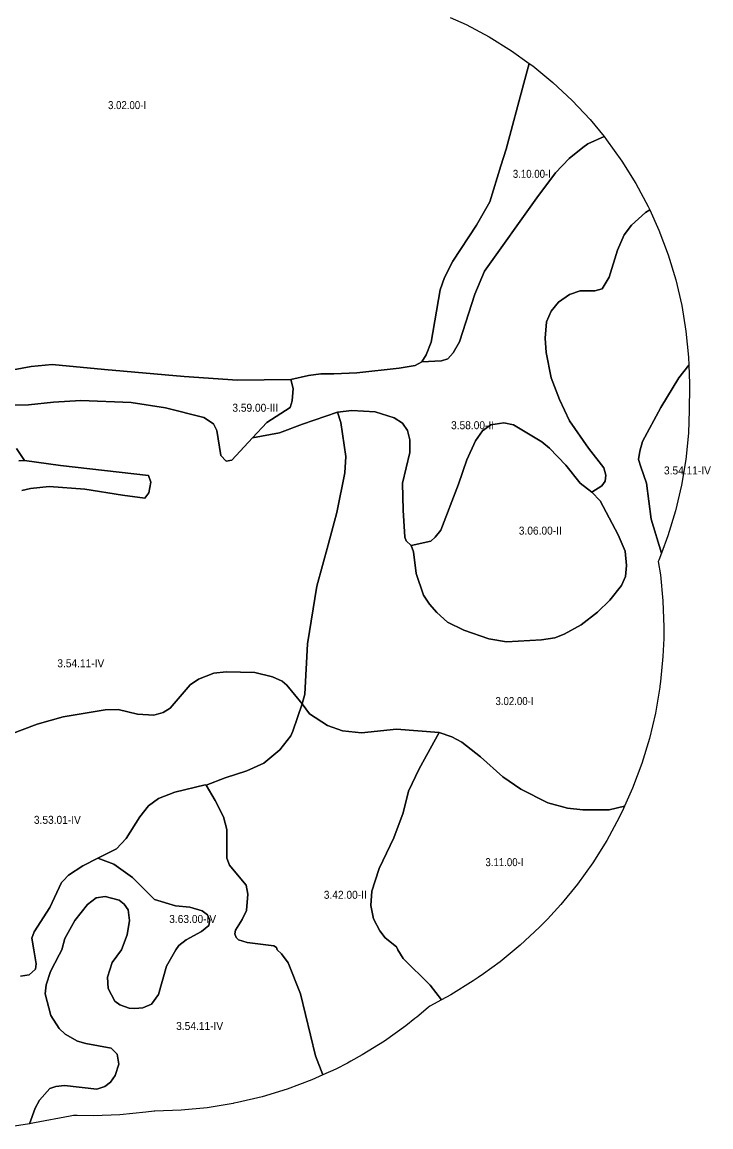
# Model space of a CAD drawing. Extents: x -591496 to -585489, y -1120610 to -1115685.
# Drawn here: x -587209 to -585489, y -1120442 to -1117681 of the extents above; entities that cross this region are included whole.
import ezdxf

# ---------------------------------------------------------------- set-up
doc = ezdxf.new("R2010")
doc.units = 0
doc.header["$LTSCALE"] = 8
doc.layers.add('40', color=7, linetype='Continuous', lineweight=25)
doc.layers.add('41', color=7, linetype='Continuous')

msp = doc.modelspace()

# ---------------------------------------------------------------- linework, layer by layer
at = {"layer": '40'}
for points in [[(-586139.893, -1117669.247), (-586100.231, -1117687.217), (-586042.52, -1117718.065), (-585986.95, -1117752.62), (-585942.401, -1117784.544), (-585956, -1117833.5), (-586000, -1117998.5), (-586013.5, -1118040), (-586041, -1118130), (-586074, -1118188.5), (-586133.5, -1118278.5), (-586154, -1118319), (-586165, -1118350.5), (-586187, -1118481), (-586199.5, -1118512.5), (-586211, -1118530), (-586227.5, -1118539), (-586267.5, -1118546), (-586373, -1118558), (-586430.5, -1118560.5), (-586463, -1118560.5), (-586494, -1118564.5), (-586538, -1118574), (-586670.5, -1118576), (-586804, -1118566.5), (-587003, -1118549.5), (-587133.5, -1118537), (-587186, -1118541.5), (-587277, -1118558.5)], [(-585778.5, -1118352.5), (-585760.5, -1118348), (-585742.5, -1118318.5), (-585722, -1118251), (-585705.5, -1118212.5), (-585687, -1118188.5), (-585652.5, -1118157), (-585641.639, -1118150.648), (-585618.64, -1118201.407), (-585595.59, -1118262.651), (-585576.594, -1118325.271), (-585561.735, -1118389), (-585551.075, -1118453.564), (-585544.661, -1118518.687), (-585544.009, -1118538.605)], [(-585544.009, -1118538.605), (-585568.5, -1118570.5), (-585613.5, -1118644), (-585659.5, -1118729.5), (-585666.5, -1118753.5), (-585669.5, -1118774.5), (-585663.5, -1118792.5), (-585650, -1118833), (-585638, -1118923), (-585612.459, -1119008.38), (-585619.111, -1119026.053), (-585620.493, -1119029.104), (-585614.945, -1119062.704), (-585608.531, -1119127.827), (-585606.39, -1119193.23), (-585606.611, -1119214.278), (-585606.772, -1119221.878), (-585608.691, -1119266.233), (-585614.81, -1119329.094), (-585616.34, -1119340.924), (-585616.635, -1119343.186), (-585627.295, -1119407.75), (-585642.154, -1119471.479), (-585661.15, -1119534.1), (-585684.2, -1119595.343), (-585704.651, -1119640.678), (-585742.5, -1119649.5), (-585809, -1119650), (-585847, -1119645.5), (-585896, -1119632), (-585963.5, -1119598.5), (-586008.5, -1119567), (-586064.5, -1119517.5), (-586111, -1119481), (-586136, -1119467), (-586167, -1119456.5), (-586274, -1119448.5), (-586361, -1119457), (-586408.5, -1119452), (-586446, -1119439), (-586491.5, -1119410), (-586509.5, -1119385), (-586503, -1119361), (-586496.5, -1119235), (-586472.5, -1119091), (-586444.5, -1118987.5), (-586423, -1118906.5), (-586402.5, -1118807.5), (-586400, -1118767), (-586412.5, -1118681.5), (-586421, -1118656), (-586385.5, -1118652), (-586327, -1118655), (-586280, -1118670.5), (-586259, -1118683.5), (-586246.5, -1118701.5), (-586240.5, -1118725.5), (-586241, -1118757), (-586258.5, -1118833.5), (-586257.5, -1118901), (-586253, -1118968.5), (-586249.5, -1118977.5), (-586237.5, -1118989.5), (-586231.5, -1119005), (-586225, -1119059), (-586206.5, -1119113), (-586191.5, -1119135.5), (-586173, -1119157), (-586146.5, -1119180.5), (-586105.5, -1119201), (-586043, -1119222), (-585999.5, -1119230), (-585911.5, -1119225), (-585878.5, -1119219.5), (-585855, -1119211), (-585812.5, -1119187), (-585772, -1119155.5), (-585741.5, -1119126), (-585712, -1119089), (-585702, -1119066.5), (-585699.5, -1119039.5), (-585703, -1119003.5), (-585720, -1118962.5), (-585765.5, -1118877.5), (-585786.5, -1118856), (-585761.5, -1118840), (-585753, -1118828), (-585751, -1118813), (-585756.5, -1118795), (-585794.5, -1118745.5), (-585841.5, -1118678), (-585867, -1118624), (-585887.5, -1118570), (-585900, -1118507), (-585903, -1118471), (-585899, -1118430.5), (-585888, -1118403.5), (-585869.5, -1118381), (-585842, -1118362), (-585815.5, -1118353), (-585778.5, -1118352.5)], [(-587277, -1118558.5), (-587186, -1118541.5), (-587133.5, -1118537), (-587003, -1118549.5), (-586804, -1118566.5), (-586670.5, -1118576), (-586538, -1118574), (-586531.5, -1118596.5), (-586534, -1118628), (-586539.5, -1118644), (-586598, -1118682), (-586633.572, -1118720.434), (-586685, -1118776), (-586699, -1118778), (-586712.5, -1118764.5), (-586722.5, -1118701.5), (-586731, -1118685), (-586755, -1118669), (-586850.5, -1118645), (-586936.5, -1118632), (-587062, -1118627), (-587130.5, -1118631), (-587193, -1118638), (-587237, -1118638.5)], [(-587237, -1118638.5), (-587193, -1118638), (-587130.5, -1118631), (-587062, -1118627), (-586936.5, -1118632), (-586850.5, -1118645), (-586755, -1118669), (-586731, -1118685)], [(-586633.572, -1118720.434), (-586566, -1118707.5), (-586508.5, -1118686), (-586421, -1118656), (-586412.5, -1118681.5), (-586400, -1118767), (-586402.5, -1118807.5), (-586423, -1118906.5), (-586444.5, -1118987.5), (-586472.5, -1119091), (-586496.5, -1119235), (-586503, -1119361), (-586509.5, -1119385), (-586547.5, -1119338), (-586559, -1119328), (-586583.5, -1119317), (-586627.5, -1119306.5), (-586699, -1119304.5), (-586730, -1119308.5), (-586768.5, -1119323), (-586789, -1119337.5), (-586839, -1119396), (-586856.5, -1119406.5), (-586879.5, -1119413), (-586920.5, -1119411), (-586969, -1119399), (-587001, -1119400), (-587106, -1119417.5), (-587171, -1119436), (-587271, -1119473)], [(-586731, -1118685), (-586722.5, -1118701.5), (-586712.5, -1118764.5), (-586699, -1118778), (-586685, -1118776), (-586633.572, -1118720.434)], [(-587209.5, -1118851.5), (-587188, -1118846.5), (-587141, -1118842), (-587052, -1118848), (-586958, -1118863), (-586902.5, -1118870.5), (-586892.5, -1118857.5), (-586887, -1118830.5), (-586893, -1118814), (-587112.5, -1118789.5), (-587202.5, -1118777), (-587222.5, -1118746.5)], [(-587222.5, -1118746.5), (-587202.5, -1118777), (-587217, -1118777.5)], [(-587217, -1118777.5), (-587202.5, -1118777), (-587112.5, -1118789.5), (-586893, -1118814), (-586887, -1118830.5), (-586892.5, -1118857.5), (-586902.5, -1118870.5), (-586958, -1118863), (-587052, -1118848), (-587141, -1118842), (-587188, -1118846.5), (-587209.5, -1118851.5)], [(-587271, -1119473), (-587171, -1119436), (-587106, -1119417.5), (-587001, -1119400), (-586969, -1119399), (-586920.5, -1119411), (-586879.5, -1119413), (-586856.5, -1119406.5), (-586839, -1119396), (-586789, -1119337.5), (-586768.5, -1119323), (-586730, -1119308.5), (-586699, -1119304.5), (-586627.5, -1119306.5), (-586583.5, -1119317), (-586559, -1119328), (-586547.5, -1119338), (-586509.5, -1119385), (-586532.5, -1119453.5), (-586538, -1119464.5), (-586565.5, -1119500), (-586605.5, -1119533), (-586648, -1119552), (-586702, -1119570), (-586749, -1119588), (-586751.5, -1119587.5), (-586827.5, -1119606), (-586868.5, -1119621), (-586893, -1119640), (-586915, -1119667), (-586948.5, -1119721), (-586973, -1119747.5), (-587019.5, -1119770.5), (-587057.5, -1119789.5), (-587093, -1119813), (-587106.513, -1119826.9), (-587110.5, -1119831), (-587139.5, -1119894), (-587178.5, -1119955), (-587184.5, -1119970.5), (-587179.632, -1120000), (-587174, -1120034.5), (-587175.5, -1120048), (-587191.5, -1120062), (-587213, -1120065)], [(-586749, -1119588), (-586726.5, -1119626.5), (-586705.5, -1119667), (-586697.5, -1119698.5), (-586697.5, -1119770.5), (-586691, -1119788), (-586658.713, -1119826.9), (-586649.5, -1119838), (-586645, -1119860.5), (-586648.5, -1119901), (-586659, -1119923.5), (-586675.5, -1119950.5), (-586677.5, -1119959.5), (-586674, -1119968.5), (-586668, -1119974.5), (-586646.5, -1119981.5), (-586580, -1119990), (-586573.5, -1119993.5), (-586571.572, -1120000), (-586561, -1120009.5), (-586544, -1120032), (-586513.5, -1120109.5), (-586476, -1120264.5), (-586457.504, -1120312.061), (-586485.287, -1120324.65), (-586546.531, -1120347.7), (-586609.151, -1120366.696), (-586671.035, -1120381.187), (-586680.245, -1120383.037), (-586682.09, -1120383.405), (-586746.654, -1120394.065), (-586811.777, -1120400.479), (-586877.18, -1120402.62), (-586878.011, -1120402.62), (-586878.678, -1120402.619), (-586899.574, -1120405.595), (-586964.697, -1120412.009), (-587030.1, -1120414.15), (-587071.294, -1120413.301), (-587078.89, -1120413.33), (-587080.378, -1120413.329), (-587084.34, -1120414.125), (-587088.816, -1120415.005), (-587178.066, -1120432.335), (-587190.445, -1120434.35), (-587176, -1120395), (-587165, -1120375.5), (-587139.5, -1120346.5), (-587124.5, -1120341), (-587103, -1120338.5), (-587022, -1120347.5), (-587002, -1120341), (-586988, -1120330.5), (-586976, -1120313.5), (-586967.5, -1120285.5), (-586971, -1120260.5), (-586986.5, -1120245.5), (-587049.5, -1120234), (-587070.5, -1120227.5), (-587101.5, -1120210.5), (-587116.5, -1120196.5), (-587137, -1120163.5), (-587151, -1120109.5), (-587148.5, -1120087), (-587138, -1120053.5), (-587116.5, -1120012.5), (-587109.595, -1120000), (-587102, -1119971.5), (-587077, -1119926.5), (-587045.5, -1119886), (-587024, -1119869.5), (-587001, -1119866), (-586966, -1119875.5), (-586953.5, -1119885.5), (-586943.5, -1119899.5), (-586940.5, -1119926.5), (-586946.5, -1119962.5), (-586960.812, -1120000), (-586984, -1120031.5), (-586995.5, -1120067.5), (-586994, -1120096.5), (-586977, -1120127.5), (-586965, -1120137), (-586941.5, -1120145.5), (-586927.5, -1120146.5), (-586907.5, -1120144.5), (-586886, -1120135), (-586868.5, -1120111), (-586848.5, -1120040.5), (-586824.732, -1120000), (-586817, -1119988.5), (-586799.5, -1119975), (-586760.5, -1119953.5), (-586742.5, -1119939), (-586740, -1119925.5), (-586746, -1119912), (-586759, -1119902), (-586790, -1119893), (-586826, -1119890), (-586878.5, -1119873.5), (-586925.1, -1119826.9)], [(-586925.1, -1119826.9), (-586933.5, -1119818.5), (-586980, -1119785.5), (-587019.5, -1119770.5), (-586973, -1119747.5), (-586948.5, -1119721), (-586915, -1119667), (-586893, -1119640), (-586868.5, -1119621), (-586827.5, -1119606), (-586751.5, -1119587.5), (-586749, -1119588)], [(-587213, -1120065), (-587191.5, -1120062), (-587175.5, -1120048), (-587174, -1120034.5), (-587179.632, -1120000), (-587184.5, -1119970.5), (-587178.5, -1119955), (-587139.5, -1119894), (-587110.5, -1119831), (-587106.513, -1119826.9), (-587093, -1119813), (-587057.5, -1119789.5), (-587019.5, -1119770.5), (-586980, -1119785.5), (-586933.5, -1119818.5), (-586925.1, -1119826.9), (-586878.5, -1119873.5), (-586826, -1119890), (-586790, -1119893), (-586759, -1119902), (-586746, -1119912), (-586740, -1119925.5), (-586742.5, -1119939), (-586760.5, -1119953.5), (-586799.5, -1119975), (-586817, -1119988.5), (-586824.732, -1120000), (-586848.5, -1120040.5), (-586868.5, -1120111), (-586886, -1120135), (-586907.5, -1120144.5), (-586927.5, -1120146.5), (-586941.5, -1120145.5), (-586965, -1120137), (-586977, -1120127.5), (-586994, -1120096.5), (-586995.5, -1120067.5), (-586984, -1120031.5), (-586960.812, -1120000), (-586946.5, -1119962.5), (-586940.5, -1119926.5), (-586943.5, -1119899.5), (-586953.5, -1119885.5), (-586966, -1119875.5), (-587001, -1119866), (-587024, -1119869.5), (-587045.5, -1119886), (-587077, -1119926.5), (-587102, -1119971.5), (-587109.595, -1120000), (-587116.5, -1120012.5), (-587138, -1120053.5), (-587148.5, -1120087), (-587151, -1120109.5), (-587137, -1120163.5), (-587116.5, -1120196.5), (-587101.5, -1120210.5), (-587070.5, -1120227.5), (-587049.5, -1120234), (-586986.5, -1120245.5), (-586971, -1120260.5), (-586967.5, -1120285.5), (-586976, -1120313.5), (-586988, -1120330.5), (-587002, -1120341), (-587022, -1120347.5), (-587103, -1120338.5), (-587124.5, -1120341), (-587139.5, -1120346.5), (-587165, -1120375.5), (-587176, -1120395), (-587190.445, -1120434.35), (-587238.154, -1120442.115)]]:
    msp.add_lwpolyline(points, dxfattribs=at)
for points in [[(-585755.742, -1117967.317), (-585796, -1117985), (-585809, -1117994.5), (-585843, -1118022), (-585876.5, -1118058), (-585923.5, -1118120.5), (-586054, -1118303.5), (-586078.5, -1118361), (-586116.5, -1118480.5), (-586132, -1118507.5), (-586146, -1118522.5), (-586161.5, -1118527.5), (-586211, -1118530), (-586199.5, -1118512.5), (-586187, -1118481), (-586165, -1118350.5), (-586154, -1118319), (-586133.5, -1118278.5), (-586074, -1118188.5), (-586041, -1118130), (-586013.5, -1118040), (-586000, -1117998.5), (-585956, -1117833.5), (-585942.401, -1117784.544), (-585933.759, -1117790.737), (-585883.174, -1117832.25), (-585835.413, -1117876.983), (-585790.68, -1117924.744)], [(-585867, -1118624), (-585841.5, -1118678), (-585794.5, -1118745.5), (-585756.5, -1118795), (-585751, -1118813), (-585753, -1118828), (-585761.5, -1118840), (-585786.5, -1118856), (-585815.5, -1118833.5), (-585851, -1118788.5), (-585892, -1118746), (-585911, -1118730), (-585981.5, -1118688), (-586005.5, -1118682.5), (-586038, -1118687.5), (-586059, -1118703), (-586077, -1118728), (-586098.5, -1118775), (-586119, -1118835.5), (-586163.5, -1118950.5), (-586177, -1118968.5), (-586188, -1118978.5), (-586237.5, -1118989.5), (-586249.5, -1118977.5), (-586253, -1118968.5), (-586257.5, -1118901), (-586258.5, -1118833.5), (-586241, -1118757), (-586240.5, -1118725.5), (-586246.5, -1118701.5), (-586259, -1118683.5), (-586280, -1118670.5), (-586327, -1118655), (-586385.5, -1118652), (-586421, -1118656), (-586508.5, -1118686), (-586566, -1118707.5), (-586633.572, -1118720.434), (-586598, -1118682), (-586539.5, -1118644), (-586534, -1118628), (-586531.5, -1118596.5), (-586538, -1118574), (-586494, -1118564.5), (-586463, -1118560.5), (-586430.5, -1118560.5), (-586373, -1118558), (-586267.5, -1118546), (-586227.5, -1118539), (-586211, -1118530), (-586161.5, -1118527.5), (-586146, -1118522.5), (-586132, -1118507.5), (-586116.5, -1118480.5), (-586078.5, -1118361), (-586054, -1118303.5), (-585923.5, -1118120.5), (-585876.5, -1118058), (-585843, -1118022), (-585809, -1117994.5), (-585796, -1117985), (-585755.742, -1117967.317), (-585749.167, -1117975.329), (-585711.05, -1118028.52), (-585676.495, -1118084.09), (-585645.647, -1118141.801), (-585641.639, -1118150.648), (-585652.5, -1118157), (-585687, -1118188.5), (-585705.5, -1118212.5), (-585722, -1118251), (-585742.5, -1118318.5), (-585760.5, -1118348), (-585778.5, -1118352.5), (-585815.5, -1118353), (-585842, -1118362), (-585869.5, -1118381), (-585888, -1118403.5), (-585899, -1118430.5), (-585903, -1118471), (-585900, -1118507), (-585887.5, -1118570)], [(-585612.459, -1119008.38), (-585638, -1118923), (-585650, -1118833), (-585663.5, -1118792.5), (-585669.5, -1118774.5), (-585666.5, -1118753.5), (-585659.5, -1118729.5), (-585613.5, -1118644), (-585568.5, -1118570.5), (-585544.009, -1118538.605), (-585542.52, -1118584.09), (-585542.551, -1118592.018), (-585543.021, -1118651.298), (-585545.131, -1118708.773), (-585551.545, -1118773.896), (-585562.205, -1118838.46), (-585577.064, -1118902.189), (-585596.06, -1118964.81)], [(-585786.5, -1118856), (-585765.5, -1118877.5), (-585720, -1118962.5), (-585703, -1119003.5), (-585699.5, -1119039.5), (-585702, -1119066.5), (-585712, -1119089), (-585741.5, -1119126), (-585772, -1119155.5), (-585812.5, -1119187), (-585855, -1119211), (-585878.5, -1119219.5), (-585911.5, -1119225), (-585999.5, -1119230), (-586043, -1119222), (-586105.5, -1119201), (-586146.5, -1119180.5), (-586173, -1119157), (-586191.5, -1119135.5), (-586206.5, -1119113), (-586225, -1119059), (-586231.5, -1119005), (-586237.5, -1118989.5), (-586188, -1118978.5), (-586177, -1118968.5), (-586163.5, -1118950.5), (-586119, -1118835.5), (-586098.5, -1118775), (-586077, -1118728), (-586059, -1118703), (-586038, -1118687.5), (-586005.5, -1118682.5), (-585981.5, -1118688), (-585911, -1118730), (-585892, -1118746), (-585851, -1118788.5), (-585815.5, -1118833.5)], [(-586167, -1119456.5), (-586217, -1119547.5), (-586244, -1119603), (-586257.5, -1119657), (-586280.5, -1119720), (-586317, -1119796.5), (-586326.954, -1119826.9), (-586335.5, -1119853), (-586338, -1119889), (-586331, -1119922.5), (-586315.5, -1119952), (-586302.5, -1119970), (-586273.5, -1119992.5), (-586270.817, -1120000), (-586257.5, -1120021.5), (-586190, -1120087.5), (-586161.852, -1120124.584), (-586190.67, -1120140.089), (-586195.114, -1120144.01), (-586222.857, -1120167.462), (-586227.767, -1120171.462), (-586250.609, -1120189.523), (-586303.8, -1120227.64), (-586359.37, -1120262.195), (-586387.718, -1120277.955), (-586396.318, -1120282.555), (-586425.681, -1120297.643), (-586457.504, -1120312.061), (-586476, -1120264.5), (-586513.5, -1120109.5), (-586544, -1120032), (-586561, -1120009.5), (-586571.572, -1120000), (-586573.5, -1119993.5), (-586580, -1119990), (-586646.5, -1119981.5), (-586668, -1119974.5), (-586674, -1119968.5), (-586677.5, -1119959.5), (-586675.5, -1119950.5), (-586659, -1119923.5), (-586648.5, -1119901), (-586645, -1119860.5), (-586649.5, -1119838), (-586658.713, -1119826.9), (-586691, -1119788), (-586697.5, -1119770.5), (-586697.5, -1119698.5), (-586705.5, -1119667), (-586726.5, -1119626.5), (-586749, -1119588), (-586702, -1119570), (-586648, -1119552), (-586605.5, -1119533), (-586565.5, -1119500), (-586538, -1119464.5), (-586532.5, -1119453.5), (-586509.5, -1119385), (-586491.5, -1119410), (-586446, -1119439), (-586408.5, -1119452), (-586361, -1119457), (-586274, -1119448.5)], [(-585704.651, -1119640.678), (-585709.746, -1119651.973), (-585716.656, -1119666.103), (-585718.117, -1119669.079), (-585748.965, -1119726.79), (-585783.52, -1119782.36), (-585821.637, -1119835.551), (-585863.15, -1119886.136), (-585896.81, -1119922.647), (-585905.85, -1119931.977), (-585916.923, -1119943.227), (-585964.684, -1119987.96), (-586015.268, -1120029.473), (-586056.464, -1120059.448), (-586070.274, -1120068.968), (-586082.27, -1120077.11), (-586137.84, -1120111.665), (-586161.852, -1120124.584), (-586190, -1120087.5), (-586257.5, -1120021.5), (-586270.817, -1120000), (-586273.5, -1119992.5), (-586302.5, -1119970), (-586315.5, -1119952), (-586331, -1119922.5), (-586338, -1119889), (-586335.5, -1119853), (-586326.954, -1119826.9), (-586317, -1119796.5), (-586280.5, -1119720), (-586257.5, -1119657), (-586244, -1119603), (-586217, -1119547.5), (-586167, -1119456.5), (-586136, -1119467), (-586111, -1119481), (-586064.5, -1119517.5), (-586008.5, -1119567), (-585963.5, -1119598.5), (-585896, -1119632), (-585847, -1119645.5), (-585809, -1119650), (-585742.5, -1119649.5)]]:
    msp.add_lwpolyline(points, close=True, dxfattribs=at)

# ---------------------------------------------------------------- texts
at = {"layer": '41'}
for s, width, p in [('3.02.00-I', 0.9, (-586994.188, -1117898.563)), ('3.10.00-I', 0.9, (-585983.375, -1118070.313)), ('3.59.00-III', 0.95, (-586683.781, -1118654.875)), ('3.58.00-II', 0.95, (-586137.625, -1118698.563)), ('3.54.11-IV', 0.95, (-585606, -1118811.5)), ('3.06.00-II', 0.95, (-585968.5, -1118962)), ('3.54.11-IV', 0.95, (-587120.75, -1119293.5)), ('3.02.00-I', 0.9, (-586026.75, -1119387.938)), ('3.53.01-IV', 0.95, (-587179.313, -1119684.75)), ('3.11.00-I', 0.9, (-586051.781, -1119790.5)), ('3.42.00-II', 0.95, (-586455.438, -1119872.063)), ('3.63.00-IV', 0.95, (-586841.406, -1119932.5)), ('3.54.11-IV', 0.95, (-586824, -1120199.875))]:
    msp.add_text(s, height=20, dxfattribs=dict(at, width=width)).set_placement(p)

doc.saveas('drawing.dxf')
